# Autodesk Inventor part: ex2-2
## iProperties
Shininess: 64.0
Length Units: 11272
Angle Units: 11279
Time Units: 11290
Mass Units: 11286
Length Display Precision: 3
Angle Display Precision: 2
Compacted: True
Part Number: ex2-2
Document SubType Name: Modeling
Created: 2003-11
Designer: Elise Moss
Cost Center: 0.4 lbmass
Authority: 11.8 in^3
Manufacturer: Standard
Standards Organization: Custom
Density: 0.0
Volumn: 0.0
Area: 0.0
PropertySet Name: Model Information
Control State: 0
Master: False
Checked Out: False
SaveDate: 2003-11-10
SaveTime: 12:44
TotalMass: 0.4 lbmass
TotalVolume: 11.8 in^3
Author: Elise Moss
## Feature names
1. Extrusion1
